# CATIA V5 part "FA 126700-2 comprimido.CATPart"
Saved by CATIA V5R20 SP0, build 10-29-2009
Part number: FA 126700-2 comprimido
Revision: ANY
Definition: UNKNOWN
Nomenclature: FA 126700-2 comprimido
Source: Unknown
Bounding box of the stored display mesh (mm): x -2.8 to 2.8, y 0 to 5, z -2.8 to 2.8
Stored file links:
  C:\Users\Utente\Desktop\IO LAVORO\3D X SITO CF\CUMSA\3D files FA\FA 1267SF\FA 126700-2 comprimido.CATPart

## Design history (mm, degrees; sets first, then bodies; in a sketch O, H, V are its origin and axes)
Body1 "Cortar-Extruir1" (main body)
  Solid1: solid without history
